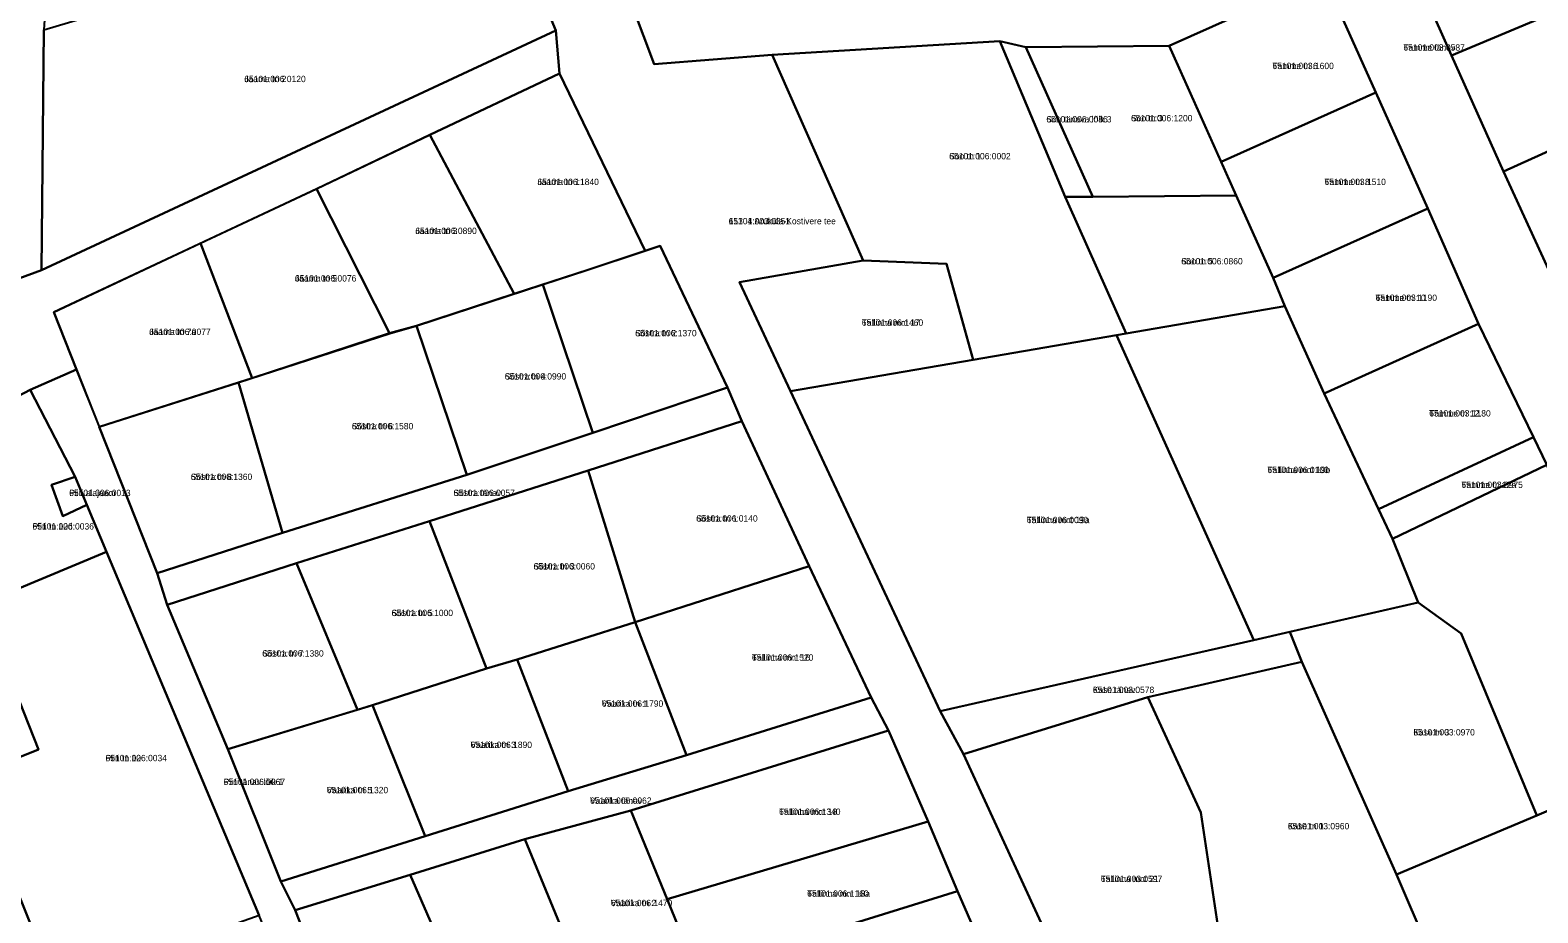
# Model space of a CAD drawing. Extents: x 556044 to 574504, y 6567077 to 6586269.
# Drawn here: x 561223.9 to 561579.8, y 6581531.9 to 6581740.3 of the extents above; entities that cross this region are included whole.
import ezdxf

# ---------------------------------------------------------------- set-up
doc = ezdxf.new("R2010")
doc.units = 0
for name, color, linetype in [('L_AADRESS', 7, 'Continuous'), ('PIIR', 7, 'Continuous'), ('TUNNUS', 7, 'Continuous')]:
    doc.layers.add(name, color=color, linetype=linetype)

msp = doc.modelspace()

# ---------------------------------------------------------------- linework, layer by layer
at = {"layer": 'PIIR'}
for points in [[(561478.64, 6581856.28), (561481.36, 6581859.76), (561521.62, 6581867.17), (561528.18, 6581861.06), (561495, 6581853.05), (561519.41, 6581806.55), (561534.52, 6581769.28), (561547.3, 6581761.62), (561559.42, 6581734.29), (561571.69, 6581706.94), (561586.8, 6581674.03), (561602.02, 6581640.64), (561617.53, 6581605.88), (561608.64, 6581601.23), (561599.83, 6581596.75), (561581.92, 6581637.63), (561578.82, 6581644.2), (561565.84, 6581670.94), (561553.84, 6581698.19), (561541.56, 6581725.59), (561529.27, 6581752.96), (561515.79, 6581761.11), (561495.54, 6581807.6)], [(561223.89, 6581853.27), (561233.7, 6581853.98), (561232.14, 6581824.92), (561230.26, 6581788.04), (561228.71, 6581764.18), (561227.16, 6581740.33), (561226.59, 6581683.63), (561217.35, 6581680.25), (561217.16, 6581719.79), (561217.89, 6581744.7), (561218.66, 6581769.3), (561219.93, 6581794.11), (561221.88, 6581825.65)], [(561547.3, 6581761.62), (561575.5, 6581773.74), (561606.63, 6581787.75), (561619, 6581759.34), (561559.42, 6581734.29)], [(561334.55, 6581772.4), (561348.03, 6581740.19), (561226.59, 6581683.63), (561227.16, 6581740.33), (561290.67, 6581759.3)], [(561366.17, 6581745.64), (561418.91, 6581745.04), (561453.39, 6581746.22), (561483.68, 6581746.55), (561488.4, 6581748.9), (561515.79, 6581761.11), (561529.27, 6581752.96), (561492.78, 6581736.58), (561458.95, 6581736.25), (561452.8, 6581737.68), (561399.08, 6581734.47), (561371.19, 6581732.22)], [(561559.42, 6581734.29), (561619, 6581759.34), (561630.95, 6581732.9), (561609.08, 6581722.9), (561608.75, 6581723.65), (561571.69, 6581706.94)], [(561529.27, 6581752.96), (561541.56, 6581725.59), (561505.07, 6581709.21), (561492.78, 6581736.58)], [(561452.8, 6581737.68), (561468.28, 6581700.91), (561468.94, 6581699.33), (561482.68, 6581668.68), (561480.38, 6581668.29), (561446.49, 6581662.47), (561440.19, 6581685.09), (561420.56, 6581685.9), (561399.08, 6581734.47)], [(561452.8, 6581737.68), (561458.95, 6581736.25), (561474.8, 6581700.95), (561468.28, 6581700.91)], [(561492.78, 6581736.58), (561508.63, 6581701.28), (561474.8, 6581700.95), (561458.95, 6581736.25)], [(561348.85, 6581730.06), (561369.06, 6581688.16), (561355.89, 6581683.76), (561338.16, 6581678.05), (561318.25, 6581715.55)], [(561541.56, 6581725.59), (561553.84, 6581698.19), (561517.34, 6581681.83), (561508.63, 6581701.28), (561505.07, 6581709.21)], [(561586.8, 6581674.03), (561571.69, 6581706.94), (561608.75, 6581723.65), (561609.08, 6581722.9), (561624.29, 6581689.34)], [(561291.52, 6581702.82), (561318.25, 6581715.55), (561338.16, 6581678.05), (561315.15, 6581670.45), (561308.7, 6581668.71)], [(561264.11, 6581689.97), (561291.52, 6581702.82), (561308.7, 6581668.71), (561276.29, 6581658.16)], [(561508.63, 6581701.28), (561517.34, 6581681.83), (561520.1, 6581675.09), (561482.68, 6581668.68), (561468.94, 6581699.33), (561468.28, 6581700.91), (561474.8, 6581700.95)], [(561553.84, 6581698.19), (561565.84, 6581670.94), (561529.37, 6581654.52), (561520.1, 6581675.09), (561517.34, 6581681.83)], [(561229.49, 6581673.73), (561264.11, 6581689.97), (561276.29, 6581658.16), (561273.11, 6581657.13), (561240.24, 6581646.66), (561234.87, 6581660.18)], [(561356.73, 6581645.25), (561344.97, 6581680.24), (561355.05, 6581683.55), (561369.06, 6581688.16), (561372.63, 6581689.33), (561388.51, 6581655.94)], [(561446.49, 6581662.47), (561403.41, 6581655.08), (561391.38, 6581680.8), (561420.56, 6581685.9), (561440.19, 6581685.09)], [(561326.96, 6581635.33), (561315.15, 6581670.45), (561344.97, 6581680.24), (561356.73, 6581645.25)], [(561480.38, 6581668.29), (561482.68, 6581668.68), (561520.1, 6581675.09), (561529.37, 6581654.52), (561542.23, 6581627.19), (561545.48, 6581620.2), (561551.59, 6581605.18), (561521.28, 6581598.24), (561512.8, 6581596.3)], [(561273.11, 6581657.13), (561308.79, 6581668.66), (561315.15, 6581670.45), (561326.96, 6581635.33), (561283.45, 6581621.62)], [(561565.84, 6581670.94), (561578.82, 6581644.2), (561542.23, 6581627.19), (561529.37, 6581654.52)], [(561480.38, 6581668.29), (561512.8, 6581596.3), (561438.73, 6581579.49), (561403.41, 6581655.08), (561446.49, 6581662.47)], [(561223.92, 6581655.37), (561234.85, 6581660.17), (561240.21, 6581646.64), (561253.85, 6581612.07), (561256.23, 6581604.63), (561270.59, 6581570.5), (561283.11, 6581539.32), (561286.45, 6581532.52), (561301.68, 6581494), (561315.26, 6581461.77), (561305.66, 6581457.75), (561306.65, 6581460.65), (561305.98, 6581463.86), (561277.97, 6581531.26), (561241.95, 6581617.15), (561237.31, 6581628.21), (561234.5, 6581634.79)], [(561171.98, 6581597.55), (561211.35, 6581618.25), (561201.11, 6581637.72), (561198.78, 6581642.15), (561223.92, 6581655.37), (561234.5, 6581634.79), (561228.93, 6581632.93), (561231.61, 6581625.51), (561237.31, 6581628.21), (561241.95, 6581617.15), (561212.25, 6581604.8), (561175.27, 6581589.41)], [(561240.21, 6581646.64), (561273.11, 6581657.13), (561283.45, 6581621.62), (561253.85, 6581612.07)], [(561253.85, 6581612.07), (561283.45, 6581621.62), (561326.96, 6581635.33), (561356.73, 6581645.25), (561388.51, 6581655.94), (561391.94, 6581647.98), (561355.66, 6581636.36), (561318.16, 6581624.33), (561286.81, 6581614.43), (561256.23, 6581604.63)], [(561355.66, 6581636.36), (561391.94, 6581647.98), (561407.77, 6581613.72), (561366.74, 6581600.54)], [(561542.23, 6581627.19), (561578.82, 6581644.2), (561581.92, 6581637.63), (561545.48, 6581620.2)], [(561599.83, 6581596.75), (561608.64, 6581601.23), (561621.06, 6581572.61), (561579.61, 6581554.85), (561561.76, 6581597.86), (561551.59, 6581605.18), (561545.48, 6581620.2), (561581.92, 6581637.63)], [(561237.31, 6581628.21), (561231.61, 6581625.51), (561228.93, 6581632.93), (561234.5, 6581634.79)], [(561366.74, 6581600.54), (561338.88, 6581591.67), (561331.65, 6581589.54), (561318.16, 6581624.33), (561355.66, 6581636.36)], [(561331.65, 6581589.54), (561304.72, 6581580.95), (561301.17, 6581579.82), (561286.81, 6581614.43), (561318.16, 6581624.33)], [(561241.95, 6581617.15), (561277.97, 6581531.26), (561251.22, 6581521.73), (561230.01, 6581514.18), (561220.08, 6581539.06), (561215.46, 6581537.15), (561205.42, 6581562.26), (561225.85, 6581570.44), (561212.25, 6581604.8)], [(561256.23, 6581604.63), (561286.81, 6581614.43), (561301.17, 6581579.82), (561270.59, 6581570.5)], [(561366.74, 6581600.54), (561407.77, 6581613.72), (561422.46, 6581582.74), (561378.84, 6581569.12)], [(561521.28, 6581598.24), (561551.59, 6581605.18), (561561.76, 6581597.86), (561579.61, 6581554.85), (561546.5, 6581540.96), (561524.15, 6581591.15)], [(561175.27, 6581589.41), (561212.25, 6581604.8), (561225.85, 6581570.44), (561205.42, 6581562.26), (561215.46, 6581537.15), (561220.08, 6581539.06), (561230.01, 6581514.18), (561212.14, 6581507.81), (561208.79, 6581506.62)], [(561338.88, 6581591.67), (561366.74, 6581600.54), (561378.84, 6581569.12), (561350.91, 6581560.63)], [(561438.73, 6581579.49), (561512.8, 6581596.3), (561521.28, 6581598.24), (561524.15, 6581591.15), (561487.74, 6581582.83), (561444.23, 6581569.32)], [(561317.17, 6581549.96), (561304.72, 6581580.95), (561331.65, 6581589.54), (561338.88, 6581591.67), (561350.91, 6581560.63)], [(561524.15, 6581591.15), (561546.5, 6581540.96), (561553.88, 6581523.71), (561507.33, 6581508.4), (561500.3, 6581555.59), (561487.74, 6581582.83)], [(561546.5, 6581540.96), (561579.61, 6581554.85), (561621.06, 6581572.61), (561655.95, 6581587.05), (561658.6, 6581588.19), (561673.96, 6581525.06), (561684.95, 6581483.18), (561687, 6581458.12), (561679.96, 6581455.87), (561672.27, 6581484.87), (561614.24, 6581469.57), (561600.53, 6581521.19), (561571.7, 6581512.12), (561567.42, 6581528.16), (561553.88, 6581523.71)], [(561270.59, 6581570.5), (561304.72, 6581580.95), (561317.17, 6581549.96), (561283.11, 6581539.32)], [(561283.11, 6581539.32), (561317.17, 6581549.96), (561350.91, 6581560.63), (561378.84, 6581569.12), (561422.46, 6581582.74), (561426.52, 6581574.92), (561365.73, 6581556.07), (561340.69, 6581549.29), (561313.6, 6581540.86), (561286.45, 6581532.52)], [(561444.23, 6581569.32), (561487.74, 6581582.83), (561500.3, 6581555.59), (561507.33, 6581508.4), (561509.1, 6581504.15), (561480.35, 6581490.91)], [(561426.52, 6581574.92), (561435.94, 6581553.48), (561374.28, 6581535.11), (561365.73, 6581556.07)], [(561365.73, 6581556.07), (561374.28, 6581535.11), (561381.3, 6581517.9), (561356.53, 6581510.88), (561340.69, 6581549.29)], [(561435.94, 6581553.48), (561442.81, 6581537.04), (561381.3, 6581517.9), (561374.28, 6581535.11)], [(561340.69, 6581549.29), (561356.53, 6581510.88), (561334.07, 6581503.76), (561330.23, 6581502.77), (561313.6, 6581540.86)], [(561313.6, 6581540.86), (561330.23, 6581502.77), (561301.68, 6581494), (561286.45, 6581532.52)], [(561366.8, 6581513.71), (561381.3, 6581517.9), (561442.81, 6581537.04), (561456.34, 6581506.01), (561380.12, 6581481.52)]]:
    msp.add_lwpolyline(points, close=True, dxfattribs=at)
for points in [[(561524.93, 6581307.49), (561491.73, 6581420.63), (561491.94, 6581428.14), (561478.96, 6581461.41), (561477.62, 6581460.99), (561459.15, 6581498.72), (561456.34, 6581506.01), (561442.81, 6581537.04), (561435.94, 6581553.48), (561426.52, 6581574.92), (561422.46, 6581582.74), (561407.77, 6581613.72), (561391.94, 6581647.98), (561388.51, 6581655.94), (561372.63, 6581689.33), (561369.06, 6581688.16), (561348.85, 6581730.06), (561348.03, 6581740.19), (561334.55, 6581772.4)], [(561366.17, 6581745.64), (561371.19, 6581732.22), (561399.08, 6581734.47), (561420.56, 6581685.9), (561391.38, 6581680.8), (561403.41, 6581655.08), (561438.73, 6581579.49), (561444.23, 6581569.32), (561480.35, 6581490.91), (561496.69, 6581455.44), (561514.23, 6581401.65), (561517.83, 6581395.22), (561537.73, 6581327.99)], [(561217.35, 6581680.25), (561226.59, 6581683.63), (561348.03, 6581740.19), (561348.85, 6581730.06), (561318.25, 6581715.55), (561291.57, 6581702.84), (561229.48, 6581673.72), (561234.85, 6581660.17), (561223.92, 6581655.37), (561198.78, 6581642.15)]]:
    msp.add_lwpolyline(points, dxfattribs=at)

# ---------------------------------------------------------------- texts
at = {"layer": 'L_AADRESS'}
for s, p in [('Tamme tänav', (561548.09, 6581735.44)), ('Jaama tn 2', (561274.46, 6581728.01)), ('Tamme tn 6', (561517.17, 6581731.09)), ('Soo tänava lõik 3', (561463.8, 6581718.5)), ('Soo tn 3', (561483.79, 6581718.76)), ('Soo tn 1', (561440.88, 6581709.79)), ('Jaama tn 1', (561343.66, 6581703.71)), ('Tamme tn 8', (561529.45, 6581703.71)), ('11304 Aruküla-Kostivere tee', (561388.8, 6581694.45)), ('Jaama tn 3', (561314.84, 6581692.15)), ('Soo tn 5', (561495.65, 6581684.98)), ('Jaama tn 5', (561286.41, 6581680.94)), ('Tamme tn 10', (561541.52, 6581676.36)), ('Jaama tn 7a', (561252.02, 6581668.32)), ('Sõstra tn 2', (561366.74, 6581668.01)), ('Tallinna mnt 17', (561420.23, 6581670.49)), ('Sõstra tn 4', (561335.94, 6581657.8)), ('Tamme tn 12', (561554.2, 6581649.07)), ('Sõstra tn 6', (561299.85, 6581646.04)), ('Tallinna mnt 19b', (561515.99, 6581635.71)), ('Sõstra tn 8', (561261.83, 6581634.09)), ('Tamme tn 12a', (561561.79, 6581632.2)), ('Piiri alajaam', (561233.12, 6581630.28)), ('Sõstra tänav', (561323.84, 6581630.29)), ('Piiri tn 12d', (561224.46, 6581622.39)), ('Sõstra tn 1', (561381.15, 6581624.26)), ('Tallinna mnt 19a', (561459.18, 6581623.89)), ('Sõstra tn 3', (561342.74, 6581612.95)), ('Sõstra tn 5', (561309.23, 6581601.95)), ('Sõstra tn 7', (561278.7, 6581592.4)), ('Tallinna mnt 16', (561394.3, 6581591.42)), ('Kase tänav', (561474.77, 6581583.78)), ('Vaarika tn 1', (561358.86, 6581580.54)), ('Kase tn 3', (561550.45, 6581573.77)), ('Vaarika tn 3', (561327.88, 6581570.82)), ('Piiri tn 12', (561241.7, 6581567.69)), ('Piiri tänav lõik 1', (561269.59, 6581562.06)), ('Vaarika tn 5', (561293.92, 6581560.13)), ('Vaarika tänav', (561356.09, 6581557.63)), ('Tallinna mnt 18', (561400.71, 6581555.02)), ('Kase tn 1', (561520.81, 6581551.61)), ('Tallinna mnt 21', (561476.66, 6581539.15)), ('Vaarika tn 2', (561360.99, 6581533.47)), ('Tallinna mnt 18a', (561407.35, 6581535.69))]:
    msp.add_text(s, height=1.5, dxfattribs=at).set_placement(p)
at = {"layer": 'TUNNUS'}
for s, p in [('65101:003:0587', (561548.09, 6581735.44)), ('65101:006:0120', (561274.46, 6581728.01)), ('65101:003:1600', (561517.17, 6581731.09)), ('65101:006:0086', (561463.8, 6581718.5)), ('65101:006:1200', (561483.79, 6581718.76)), ('65101:006:0002', (561440.88, 6581709.79)), ('65101:006:1840', (561343.66, 6581703.71)), ('65101:003:1510', (561529.45, 6581703.71)), ('65101:003:0351', (561388.8, 6581694.45)), ('65101:006:0890', (561314.84, 6581692.15)), ('65101:006:0860', (561495.65, 6581684.98)), ('65101:006:0076', (561286.41, 6581680.94)), ('65101:003:1190', (561541.52, 6581676.36)), ('65101:006:0077', (561252.02, 6581668.32)), ('65101:006:1370', (561366.74, 6581668.01)), ('65101:006:1460', (561420.23, 6581670.49)), ('65101:006:0990', (561335.94, 6581657.8)), ('65101:003:1180', (561554.2, 6581649.07)), ('65101:006:1580', (561299.85, 6581646.04)), ('65101:006:0100', (561515.99, 6581635.71)), ('65101:006:1360', (561261.83, 6581634.09)), ('65101:003:0975', (561561.79, 6581632.2)), ('65101:006:0013', (561233.12, 6581630.28)), ('65101:006:0057', (561323.84, 6581630.29)), ('65101:006:0036', (561224.46, 6581622.39)), ('65101:006:0140', (561381.15, 6581624.26)), ('65101:006:0090', (561459.18, 6581623.89)), ('65101:006:0060', (561342.74, 6581612.95)), ('65101:006:1000', (561309.23, 6581601.95)), ('65101:006:1380', (561278.7, 6581592.4)), ('65101:006:1520', (561394.3, 6581591.42)), ('65101:003:0578', (561474.77, 6581583.78)), ('65101:006:1790', (561358.86, 6581580.54)), ('65101:003:0970', (561550.45, 6581573.77)), ('65101:006:1890', (561327.88, 6581570.82)), ('65101:006:0034', (561241.7, 6581567.69)), ('65101:006:0067', (561269.59, 6581562.06)), ('65101:006:1320', (561293.92, 6581560.13)), ('65101:006:0062', (561356.09, 6581557.63)), ('65101:006:1340', (561400.71, 6581555.02)), ('65101:003:0960', (561520.81, 6581551.61)), ('65101:003:0597', (561476.66, 6581539.15)), ('65101:006:1470', (561360.99, 6581533.47)), ('65101:006:1160', (561407.35, 6581535.69))]:
    msp.add_text(s, height=1.5, dxfattribs=at).set_placement(p)

doc.saveas('drawing.dxf')
